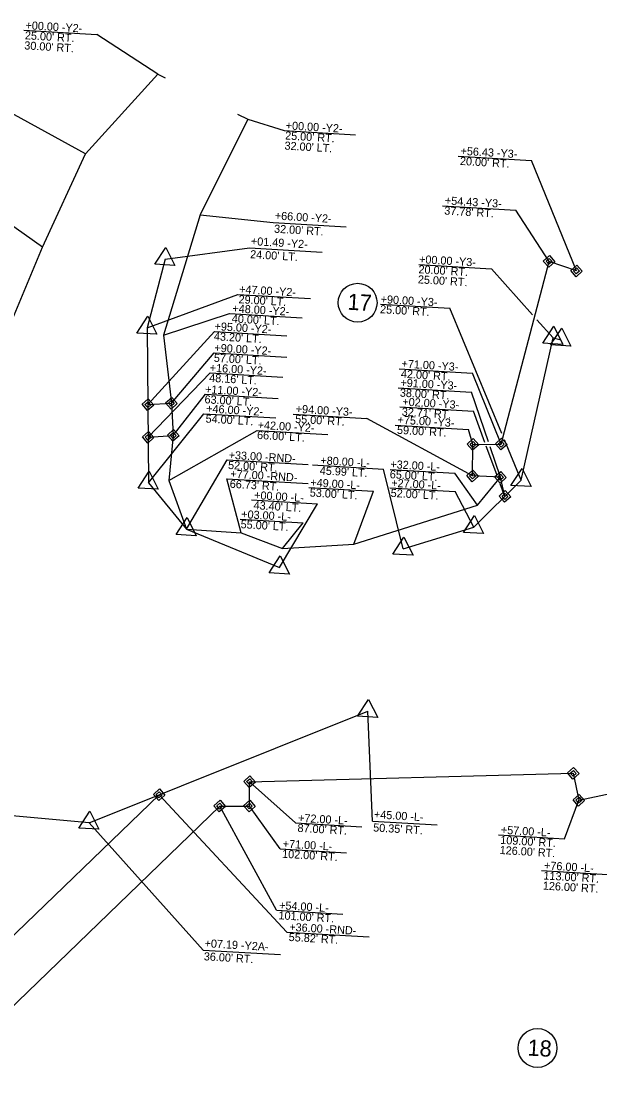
# Model space of a CAD drawing. Extents: x 2010883 to 2014849, y 442000 to 447413.
# Drawn here: x 2013173 to 2013530, y 444643 to 445303 of the extents above; entities that cross this region are included whole.
import ezdxf

# ---------------------------------------------------------------- set-up
doc = ezdxf.new("R2010")
doc.units = 0
for name, color, linetype in [('Prop Easement Construction', 7, 'Continuous'), ('Prop Easement Construction Station Offsets', 7, 'Continuous'), ('Prop Easement Permanent Drainage', 7, 'Continuous'), ('Prop Easement Permanent Drainage Station Offsets', 7, 'Continuous'), ('Prop Easement Permanent Utility', 7, 'Continuous'), ('Prop Easement Permanent Utility Station Offsets', 7, 'Continuous'), ('Prop Parcel Number CELL', 7, 'Continuous'), ('Prop Parcel Number Text', 7, 'Continuous'), ('Prop ROW Marker CELL', 7, 'Continuous'), ('Prop ROW Permanent Easement CELL', 7, 'Continuous'), ('Prop ROW RW Lines', 7, 'Continuous'), ('Prop ROW Station Offsets', 7, 'Continuous')]:
    doc.layers.add(name, color=color, linetype=linetype)

msp = doc.modelspace()

# ---------------------------------------------------------------- linework, layer by layer
at = {"layer": 'Prop Easement Construction'}
for p, q in [((2013212.33, 445221.34), (2013257.03, 445270.55)), ((2013257.03, 445270.55), (2013261.5, 445268.32)), ((2013312.49, 445242.85), (2013283.02, 445183.84)), ((2013306.23, 445245.97), (2013312.49, 445242.85)), ((2013185.64, 445163.8), (2013212.33, 445221.34)), ((2013283.02, 445183.84), (2013260.5, 445109.5)), ((2013166.15, 445116.84), (2013185.64, 445163.8)), ((2013260.5, 445109.5), (2013265.33, 445067.46)), ((2013266.47, 445047.57), (2013263.68, 445019.72)), ((2013263.68, 445019.72), (2013274.7, 444989.63)), ((2013454.49, 445004.62), (2013468.6, 445021.8)), ((2013378.09, 444980.48), (2013454.49, 445004.62)), ((2013274.7, 444989.63), (2013308.41, 444987.54)), ((2013308.41, 444987.54), (2013334.04, 444977.79)), ((2013334.04, 444977.79), (2013378.09, 444980.48))]:
    msp.add_line(p, q, dxfattribs=at)
at = {"layer": 'Prop Easement Construction Station Offsets'}
for p, q in [((2013174.1, 445297.68), (2013219.23, 445295.02)), ((2013257.03, 445270.55), (2013219.23, 445295.02)), ((2013212.33, 445221.34), (2013120.91, 445271.5)), ((2013312.49, 445242.85), (2013335.07, 445235.75)), ((2013335.07, 445235.75), (2013379, 445233.16)), ((2013185.64, 445163.8), (2013125.32, 445205.97)), ((2013283.02, 445183.84), (2013328.3, 445179.09)), ((2013328.3, 445179.09), (2013373.33, 445176.44)), ((2013260.5, 445109.5), (2013301.31, 445122.89)), ((2013301.31, 445122.89), (2013346.19, 445120.24)), ((2013263.68, 445019.72), (2013318.41, 445050.68)), ((2013318.41, 445050.68), (2013362.01, 445048.11)), ((2013400.46, 445026.6), (2013440.39, 445024.25)), ((2013454.49, 445004.62), (2013440.39, 445024.25)), ((2013299.64, 445020.81), (2013349.78, 445017.86)), ((2013308.41, 444987.54), (2013299.64, 445020.81)), ((2013350.29, 445015.45), (2013390.22, 445013.1)), ((2013378.09, 444980.48), (2013390.22, 445013.1)), ((2013307.76, 444995.95), (2013346.64, 444993.66)), ((2013334.04, 444977.79), (2013346.64, 444993.66))]:
    msp.add_line(p, q, dxfattribs=at)
at = {"layer": 'Prop Easement Permanent Drainage'}
for p, q in [((2013250.81, 445066.58), (2013265.33, 445067.46)), ((2013265.33, 445067.46), (2013266.47, 445047.57)), ((2013250.98, 445046.48), (2013266.47, 445047.57))]:
    msp.add_line(p, q, dxfattribs=at)
at = {"layer": 'Prop Easement Permanent Drainage Station Offsets'}
for p, q in [((2013250.81, 445066.58), (2013291.87, 445111.8)), ((2013291.87, 445111.8), (2013336.75, 445109.16)), ((2013265.33, 445067.46), (2013291.78, 445098.5)), ((2013291.78, 445098.5), (2013336.67, 445095.86)), ((2013250.98, 445046.48), (2013289.21, 445086.29)), ((2013289.21, 445086.29), (2013334.1, 445083.64)), ((2013266.47, 445047.57), (2013286.33, 445073.01)), ((2013286.33, 445073.01), (2013331.21, 445070.37))]:
    msp.add_line(p, q, dxfattribs=at)
at = {"layer": 'Prop Easement Permanent Utility'}
for p, q in [((2013469.07, 445042.19), (2013498.67, 445155.02)), ((2013515.58, 445149.19), (2013498.67, 445155.02)), ((2013451.36, 445022.59), (2013451.61, 445042.01)), ((2013451.61, 445042.01), (2013469.07, 445042.19)), ((2013468.6, 445021.8), (2013451.36, 445022.59)), ((2013471.36, 445009.91), (2013468.6, 445021.8)), ((2013313.62, 444833.81), (2013513.54, 444839)), ((2013513.54, 444839), (2013517.04, 444822.36)), ((2013313.52, 444818.77), (2013313.62, 444833.81)), ((2013097.33, 444670.95), (2013257.77, 444825.74)), ((2013517.04, 444822.36), (2013537.4, 444826.79)), ((2013113.33, 444643.09), (2013295.16, 444818.72)), ((2013295.16, 444818.72), (2013313.52, 444818.77))]:
    msp.add_line(p, q, dxfattribs=at)
at = {"layer": 'Prop Easement Permanent Utility Station Offsets'}
for p, q in [((2013442.48, 445219.99), (2013487.84, 445217.32)), ((2013515.58, 445149.19), (2013487.84, 445217.32)), ((2013432.8, 445189.35), (2013478.16, 445186.68)), ((2013498.67, 445155.02), (2013478.16, 445186.68)), ((2013406.02, 445088.61), (2013451.39, 445085.94)), ((2013469.07, 445042.19), (2013451.39, 445085.94)), ((2013405.34, 445076.95), (2013450.7, 445074.27)), ((2013461.18, 445043.56), (2013450.7, 445074.27)), ((2013406.51, 445065.17), (2013451.88, 445062.5)), ((2013458.99, 445043.3), (2013451.88, 445062.5)), ((2013340.66, 445060.75), (2013386.03, 445058.07)), ((2013451.36, 445022.59), (2013386.03, 445058.07)), ((2013403.58, 445053.99), (2013448.95, 445051.32)), ((2013451.61, 445042.01), (2013448.95, 445051.32)), ((2013466.34, 445023.47), (2013459.86, 445040.95)), ((2013468.6, 445021.8), (2013462.18, 445040.61)), ((2013471.36, 445009.91), (2013468.44, 445017.79)), ((2013342.05, 444808.34), (2013313.62, 444833.81)), ((2013336.64, 444741.01), (2013257.77, 444825.74)), ((2013330.34, 444754.4), (2013295.16, 444818.72)), ((2013332.58, 444792.4), (2013313.52, 444818.77)), ((2013508.23, 444798.54), (2013517.04, 444822.36)), ((2013342.05, 444808.34), (2013382.94, 444805.93)), ((2013467.34, 444800.95), (2013508.23, 444798.54)), ((2013332.58, 444792.4), (2013373.47, 444789.99)), ((2013494.02, 444778.97), (2013534.91, 444776.56)), ((2013330.34, 444754.4), (2013371.23, 444751.99)), ((2013336.64, 444741.01), (2013387.59, 444738))]:
    msp.add_line(p, q, dxfattribs=at)
at = {"layer": 'Prop Parcel Number CELL'}
for p, q in [((2013380.38, 445129.5), (2013380.38, 445129.5)), ((2013491.48, 444669.4), (2013491.48, 444669.4))]:
    msp.add_line(p, q, dxfattribs=at)
for centre in [(2013380.38, 445129.5), (2013491.48, 444669.4)]:
    msp.add_circle(centre, 12, dxfattribs=at)
at = {"layer": 'Prop ROW Marker CELL'}
for p, q in [((2013261.5, 445156.43), (2013261.5, 445156.43)), ((2013498.67, 445155.02), (2013498.67, 445155.02)), ((2013515.58, 445149.19), (2013515.58, 445149.19)), ((2013250.41, 445113.99), (2013250.41, 445113.99)), ((2013501.18, 445107.76), (2013501.18, 445107.76)), ((2013506.06, 445106.67), (2013506.06, 445106.67)), ((2013250.81, 445066.58), (2013250.81, 445066.58)), ((2013265.33, 445067.46), (2013265.33, 445067.46)), ((2013250.98, 445046.48), (2013250.98, 445046.48)), ((2013266.47, 445047.57), (2013266.47, 445047.57)), ((2013451.61, 445042.01), (2013451.61, 445042.01)), ((2013469.07, 445042.19), (2013469.07, 445042.19)), ((2013451.36, 445022.59), (2013451.36, 445022.59)), ((2013251.22, 445018.3), (2013251.22, 445018.3)), ((2013468.6, 445021.8), (2013468.6, 445021.8)), ((2013481.5, 445019.94), (2013481.5, 445019.94)), ((2013471.36, 445009.91), (2013471.36, 445009.91)), ((2013274.7, 444989.63), (2013274.7, 444989.63)), ((2013452.2, 444990.97), (2013452.2, 444990.97)), ((2013408.58, 444977.57), (2013408.58, 444977.57)), ((2013332.18, 444965.98), (2013332.18, 444965.98)), ((2013386.74, 444877.41), (2013386.74, 444877.41)), ((2013513.54, 444839), (2013513.54, 444839)), ((2013313.62, 444833.81), (2013313.62, 444833.81)), ((2013257.77, 444825.74), (2013257.77, 444825.74)), ((2013295.16, 444818.72), (2013295.16, 444818.72)), ((2013313.52, 444818.77), (2013313.52, 444818.77)), ((2013517.04, 444822.36), (2013517.04, 444822.36)), ((2013214.55, 444808.42), (2013214.55, 444808.42))]:
    msp.add_line(p, q, dxfattribs=at)
for points in [[(2013255.05, 445153.21), (2013261.92, 445163.62), (2013267.53, 445152.47)], [(2013243.96, 445110.76), (2013250.83, 445121.17), (2013256.44, 445110.03)], [(2013494.73, 445104.53), (2013501.6, 445114.95), (2013507.21, 445103.8)], [(2013499.61, 445103.44), (2013506.48, 445113.85), (2013512.08, 445102.71)], [(2013244.77, 445015.08), (2013251.65, 445025.49), (2013257.25, 445014.34)], [(2013475.05, 445016.71), (2013481.93, 445027.12), (2013487.53, 445015.98)], [(2013268.25, 444986.41), (2013275.13, 444996.82), (2013280.73, 444985.67)], [(2013445.75, 444987.74), (2013452.62, 444998.15), (2013458.22, 444987)], [(2013402.13, 444974.34), (2013409.01, 444984.76), (2013414.61, 444973.61)], [(2013325.73, 444962.76), (2013332.6, 444973.17), (2013338.2, 444962.02)], [(2013380.29, 444874.19), (2013387.17, 444884.6), (2013392.77, 444873.45)], [(2013208.1, 444805.19), (2013214.97, 444815.6), (2013220.58, 444804.45)]]:
    msp.add_lwpolyline(points, close=True, dxfattribs=at)
at = {"layer": 'Prop ROW Permanent Easement CELL'}
for points in [[(2013498.89, 445158.61), (2013502.27, 445154.81), (2013498.46, 445151.43), (2013495.08, 445155.23)], [(2013498.78, 445156.82), (2013500.47, 445154.91), (2013498.57, 445153.22), (2013496.88, 445155.12)], [(2013515.79, 445152.78), (2013519.18, 445148.98), (2013515.37, 445145.59), (2013511.99, 445149.4)], [(2013515.69, 445150.98), (2013517.38, 445149.08), (2013515.48, 445147.39), (2013513.79, 445149.29)], [(2013251.02, 445070.17), (2013254.41, 445066.36), (2013250.6, 445062.98), (2013247.22, 445066.79)], [(2013265.54, 445071.05), (2013268.93, 445067.24), (2013265.12, 445063.86), (2013261.74, 445067.67)], [(2013265.44, 445069.25), (2013267.13, 445067.35), (2013265.23, 445065.66), (2013263.53, 445067.56)], [(2013250.92, 445068.37), (2013252.61, 445066.47), (2013250.71, 445064.78), (2013249.02, 445066.68)], [(2013251.19, 445050.07), (2013254.58, 445046.27), (2013250.77, 445042.89), (2013247.39, 445046.69)], [(2013266.68, 445051.16), (2013270.06, 445047.35), (2013266.26, 445043.97), (2013262.88, 445047.78)], [(2013266.58, 445049.36), (2013268.27, 445047.46), (2013266.36, 445045.77), (2013264.67, 445047.67)], [(2013251.09, 445048.28), (2013252.78, 445046.37), (2013250.88, 445044.68), (2013249.19, 445046.59)], [(2013451.82, 445045.6), (2013455.2, 445041.79), (2013451.39, 445038.41), (2013448.01, 445042.22)], [(2013451.71, 445043.8), (2013453.4, 445041.9), (2013451.5, 445040.21), (2013449.81, 445042.11)], [(2013469.28, 445045.79), (2013472.66, 445041.98), (2013468.86, 445038.6), (2013465.48, 445042.41)], [(2013469.17, 445043.99), (2013470.87, 445042.09), (2013468.96, 445040.4), (2013467.27, 445042.3)], [(2013451.57, 445026.19), (2013454.95, 445022.38), (2013451.14, 445019), (2013447.76, 445022.8)], [(2013451.46, 445024.39), (2013453.15, 445022.49), (2013451.25, 445020.8), (2013449.56, 445022.7)], [(2013468.81, 445025.4), (2013472.19, 445021.59), (2013468.39, 445018.21), (2013465.01, 445022.01)], [(2013468.71, 445023.6), (2013470.4, 445021.7), (2013468.49, 445020.01), (2013466.8, 445021.91)], [(2013471.57, 445013.51), (2013474.96, 445009.7), (2013471.15, 445006.32), (2013467.77, 445010.12)], [(2013471.47, 445011.71), (2013473.16, 445009.81), (2013471.26, 445008.12), (2013469.57, 445010.02)], [(2013513.75, 444842.59), (2013517.14, 444838.79), (2013513.33, 444835.41), (2013509.95, 444839.21)], [(2013513.65, 444840.8), (2013515.34, 444838.89), (2013513.44, 444837.2), (2013511.75, 444839.1)], [(2013313.84, 444837.41), (2013317.22, 444833.6), (2013313.41, 444830.22), (2013310.03, 444834.02)], [(2013313.73, 444835.61), (2013315.42, 444833.71), (2013313.52, 444832.02), (2013311.83, 444833.92)], [(2013257.99, 444829.33), (2013261.37, 444825.52), (2013257.56, 444822.14), (2013254.18, 444825.95)], [(2013257.88, 444827.53), (2013259.57, 444825.63), (2013257.67, 444823.94), (2013255.98, 444825.84)], [(2013517.25, 444825.95), (2013520.63, 444822.15), (2013516.83, 444818.77), (2013513.44, 444822.57)], [(2013295.38, 444822.31), (2013298.76, 444818.51), (2013294.95, 444815.13), (2013291.57, 444818.93)], [(2013295.27, 444820.52), (2013296.96, 444818.61), (2013295.06, 444816.92), (2013293.37, 444818.83)], [(2013313.73, 444822.37), (2013317.11, 444818.56), (2013313.31, 444815.18), (2013309.92, 444818.99)], [(2013313.62, 444820.57), (2013315.31, 444818.67), (2013313.41, 444816.98), (2013311.72, 444818.88)], [(2013517.14, 444824.16), (2013518.83, 444822.26), (2013516.93, 444820.57), (2013515.24, 444822.47)]]:
    msp.add_lwpolyline(points, close=True, dxfattribs=at)
at = {"layer": 'Prop ROW RW Lines'}
for p, q in [((2013261.5, 445156.43), (2013250.41, 445113.99)), ((2013250.41, 445113.99), (2013251.22, 445018.3)), ((2013481.5, 445019.94), (2013501.18, 445107.76)), ((2013501.18, 445107.76), (2013506.06, 445106.67)), ((2013251.22, 445018.3), (2013274.7, 444989.63)), ((2013452.2, 444990.97), (2013481.5, 445019.94)), ((2013274.7, 444989.63), (2013332.18, 444965.98)), ((2013408.58, 444977.57), (2013452.2, 444990.97)), ((2013214.55, 444808.42), (2013386.74, 444877.41)), ((2013214.55, 444808.42), (2013138.85, 444815.21))]:
    msp.add_line(p, q, dxfattribs=at)
at = {"layer": 'Prop ROW Station Offsets'}
for p, q in [((2013261.5, 445156.43), (2013313.52, 445163.36)), ((2013313.52, 445163.36), (2013358.44, 445160.71)), ((2013418.2, 445153.15), (2013463.12, 445150.51)), ((2013488.5, 445122), (2013463.12, 445150.51)), ((2013250.41, 445113.99), (2013306.32, 445134.68)), ((2013306.32, 445134.68), (2013351.24, 445132.03)), ((2013394.46, 445128.57), (2013437.25, 445126.05)), ((2013469.51, 445048.69), (2013437.25, 445126.05)), ((2013501.18, 445107.76), (2013491.13, 445119.04)), ((2013251.22, 445018.3), (2013285.36, 445061)), ((2013285.36, 445061), (2013329.92, 445058.37)), ((2013481.5, 445019.94), (2013471.11, 445044.87)), ((2013274.7, 444989.63), (2013299.85, 445032.55)), ((2013299.85, 445032.55), (2013349.76, 445029.6)), ((2013352.46, 445029.33), (2013396.38, 445026.74)), ((2013408.58, 444977.57), (2013396.38, 445026.74)), ((2013400.3, 445015.32), (2013440.68, 445012.94)), ((2013452.2, 444990.97), (2013440.68, 445012.94)), ((2013314.91, 445007.76), (2013355.52, 445005.36)), ((2013332.18, 444965.98), (2013355.52, 445005.36)), ((2013389.54, 444809.43), (2013386.74, 444877.41)), ((2013284.9, 444729.9), (2013214.55, 444808.42)), ((2013389.54, 444809.43), (2013429.47, 444807.08)), ((2013284.9, 444729.9), (2013332.82, 444727.07))]:
    msp.add_line(p, q, dxfattribs=at)

# ---------------------------------------------------------------- texts
at = {"layer": 'Prop Easement Construction Station Offsets'}
for s, p in [('+00.00 -Y2-', (2013175.09, 445298.42)), ("25.00' RT.", (2013174.73, 445292.18)), ("30.00' RT.", (2013174.36, 445285.94)), ('+00.00 -Y2-', (2013335.85, 445236.56)), ("25.00' RT.", (2013335.48, 445230.32)), ("32.00' LT.", (2013335.11, 445224.08)), ('+66.00 -Y2-', (2013329.13, 445180.88)), ("32.00' RT.", (2013328.65, 445172.77)), ('+48.00 -Y2-', (2013302.91, 445123.6)), ("40.00' LT.", (2013302.55, 445117.36)), ('+42.00 -Y2-', (2013318.52, 445051.68)), ("66.00' LT.", (2013318.15, 445045.44)), ('+32.00 -L-', (2013400.5, 445027.44)), ('+77.00 -RND-', (2013301.64, 445021.52)), ("65.00' LT.", (2013400.13, 445021.21)), ("66.73' RT.", (2013301.27, 445015.28)), ('+49.00 -L-', (2013351.06, 445016.13)), ("53.00' LT.", (2013350.69, 445009.89)), ('+03.00 -L-', (2013308.37, 444996.6)), ("55.00' LT.", (2013308.01, 444990.36))]:
    msp.add_text(s, height=5, rotation=356.62643, dxfattribs=at).set_placement(p)
at = {"layer": 'Prop Easement Permanent Drainage Station Offsets'}
for s, p in [('+95.00 -Y2-', (2013291.88, 445112.6)), ("43.20' LT.", (2013291.51, 445106.36)), ('+90.00 -Y2-', (2013291.8, 445099.3)), ("57.00' LT.", (2013291.43, 445093.06)), ('+16.00 -Y2-', (2013288.94, 445086.97)), ("48.16' LT.", (2013288.57, 445080.74)), ('+11.00 -Y2-', (2013286.05, 445073.7)), ("63.00' LT.", (2013285.69, 445067.46))]:
    msp.add_text(s, height=5, rotation=356.62643, dxfattribs=at).set_placement(p)
at = {"layer": 'Prop Easement Permanent Utility Station Offsets'}
for s, p in [('+56.43 -Y3-', (2013443.86, 445220.84)), ("20.00' RT.", (2013443.49, 445214.61)), ('+54.43 -Y3-', (2013434.18, 445190.2)), ("37.78' RT.", (2013433.81, 445183.97)), ('+71.00 -Y3-', (2013407.4, 445089.47)), ('+91.00 -Y3-', (2013406.71, 445077.8)), ("42.00' RT.", (2013407.03, 445083.23)), ("38.00' RT.", (2013406.35, 445071.56)), ('+02.00 -Y3-', (2013407.89, 445066.03)), ('+94.00 -Y3-', (2013342.04, 445061.6)), ("32.71' RT.", (2013407.52, 445059.79)), ("55.00' RT.", (2013341.67, 445055.36)), ('+75.00 -Y3-', (2013404.96, 445054.85)), ("59.00' RT.", (2013404.59, 445048.61)), ('+72.00 -L-', (2013343.48, 444809.07)), ("87.00' RT.", (2013343.11, 444802.83)), ('+57.00 -L-', (2013468.77, 444801.68)), ("109.00' RT.", (2013468.4, 444795.44)), ("102.00' RT.", (2013333.64, 444786.89)), ('+71.00 -L-', (2013334.01, 444793.13)), ("126.00' RT.", (2013468.03, 444789.2)), ("113.00' RT.", (2013495.08, 444773.46)), ('+76.00 -L-', (2013495.45, 444779.7)), ("126.00' RT.", (2013494.71, 444767.22)), ('+54.00 -L-', (2013331.77, 444755.13)), ("101.00' RT.", (2013331.4, 444748.89)), ('+36.00 -RND-', (2013338.07, 444741.74)), ("55.82' RT.", (2013337.7, 444735.5))]:
    msp.add_text(s, height=5, rotation=356.62643, dxfattribs=at).set_placement(p)
at = {"layer": 'Prop Parcel Number Text'}
for s, p in [('17', (2013373.92, 445125.23)), ('18', (2013485.14, 444664.78))]:
    msp.add_text(s, height=10, rotation=356.62643, dxfattribs=at).set_placement(p)
at = {"layer": 'Prop ROW Station Offsets'}
for s, p in [('+01.49 -Y2-', (2013314.35, 445165.14)), ("24.00' LT.", (2013313.87, 445157.03)), ('+00.00 -Y3-', (2013418.22, 445153.97)), ("20.00' RT.", (2013417.86, 445147.73)), ("25.00' RT.", (2013417.49, 445141.49)), ('+47.00 -Y2-', (2013307.09, 445135.46)), ("29.00' LT.", (2013306.72, 445129.22)), ('+90.00 -Y3-', (2013394.5, 445129.31)), ("25.00' RT.", (2013394.14, 445123.08)), ('+46.00 -Y2-', (2013286.73, 445061.78)), ("54.00' LT.", (2013286.36, 445055.54)), ('+33.00 -RND-', (2013300.61, 445033.14)), ("52.00' RT.", (2013300.24, 445026.9)), ('+80.00 -L-', (2013357.26, 445029.79)), ("45.99' LT.", (2013356.89, 445023.56)), ('+27.00 -L-', (2013401.06, 445015.89)), ('+00.00 -L-', (2013316.37, 445008.33)), ("52.00' LT.", (2013400.69, 445009.65)), ("43.40' LT.", (2013316, 445002.09)), ('+45.00 -L-', (2013390.37, 444811.22)), ("50.35' RT.", (2013389.89, 444803.11)), ('+07.19 -Y2A-', (2013285.73, 444731.68)), ("36.00' RT.", (2013285.25, 444723.57))]:
    msp.add_text(s, height=5, rotation=356.62643, dxfattribs=at).set_placement(p)

doc.saveas('drawing.dxf')
